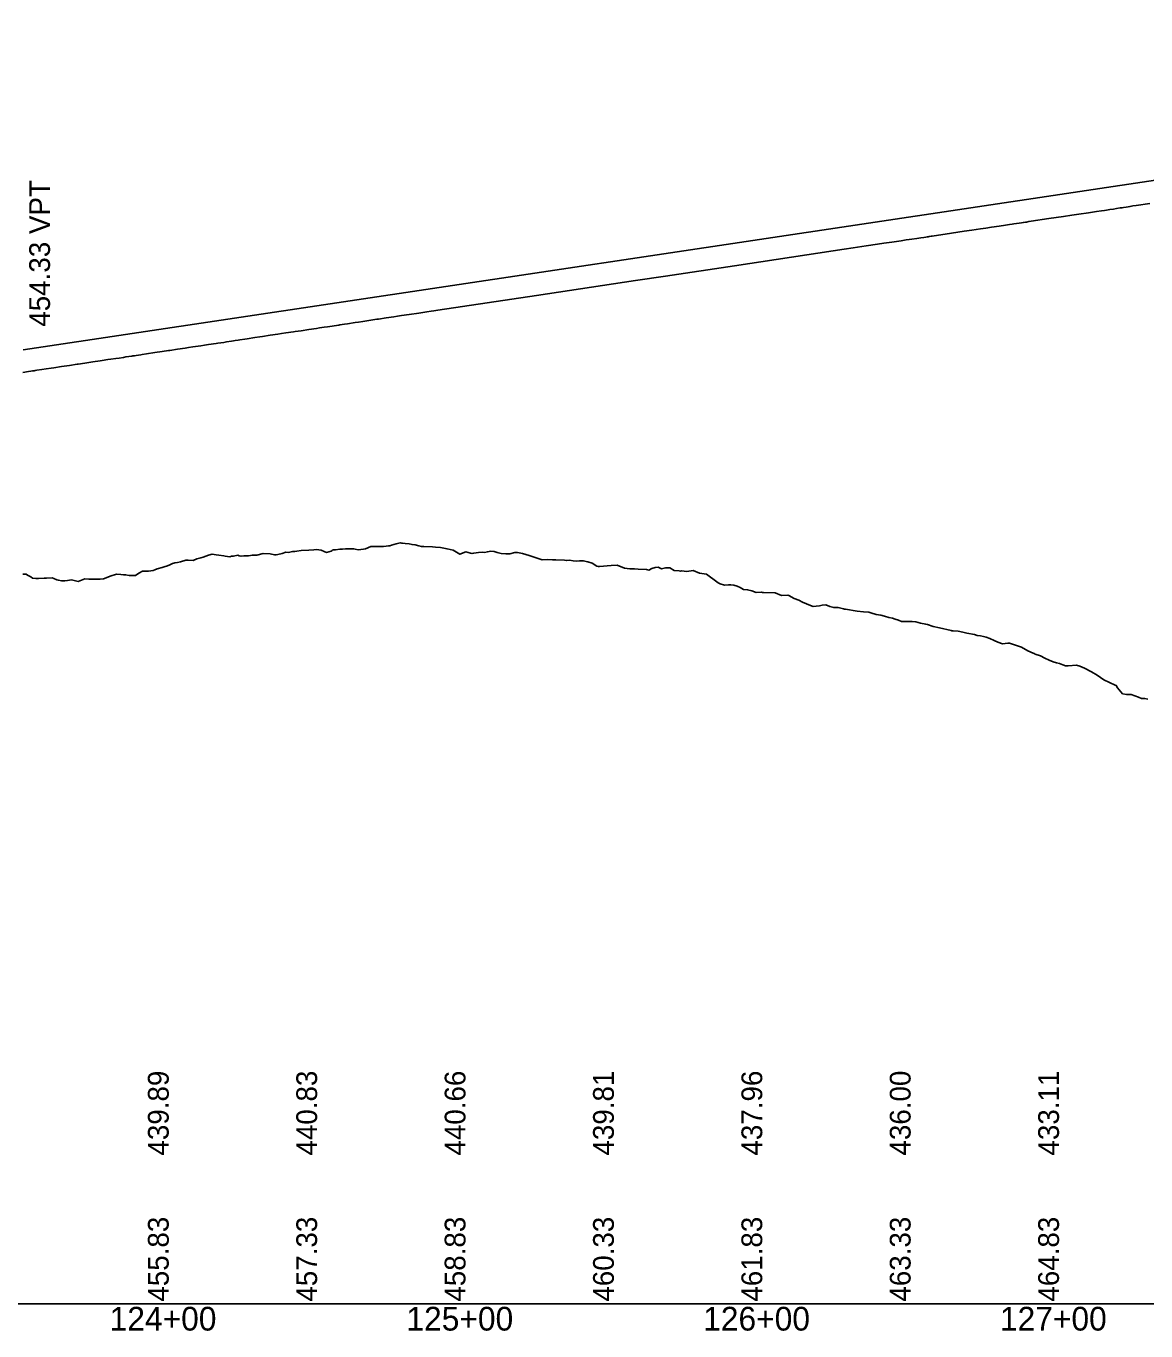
# Model space of a CAD drawing. Extents: x 2017200 to 2047700, y 854850 to 893350.
# Drawn here: x 2021850.9 to 2022228.3, y 865090.9 to 865530.8 of the extents above; entities that cross this region are included whole.
import ezdxf

# ---------------------------------------------------------------- set-up
doc = ezdxf.new("R2010")
doc.units = 0
for name, color, linetype in [('RD_DDB_Profile_Elev', 7, 'Continuous'), ('RD_DDB_Profile_EX', 7, 'Continuous'), ('RD_DDB_Profile_PR', 7, 'Continuous'), ('RD_DDB_StaTX', 7, 'Continuous'), ('RD_DDB_StripGrade', 7, 'Continuous'), ('RD_GPK_Profile_Cell', 7, 'Continuous')]:
    doc.layers.add(name, color=color, linetype=linetype)

msp = doc.modelspace()

# ---------------------------------------------------------------- linework, layer by layer
at = {"layer": 'RD_DDB_Profile_Elev'}
msp.add_lwpolyline([(2021849.9, 865414.03), (2021851.7, 865414.3), (2021852.5, 865414.42), (2021853.06, 865414.5), (2021853.66, 865414.59), (2021854.04, 865414.65), (2021854.57, 865414.73), (2021856.29, 865415), (2021857.71, 865415.21), (2021859.41, 865415.47), (2021860.32, 865415.6), (2021862.92, 865415.99), (2021864.66, 865416.25), (2021865.52, 865416.38), (2021868.13, 865416.77), (2021868.5, 865416.83), (2021870.73, 865417.16), (2021873.48, 865417.57), (2021875.94, 865417.94), (2021876.55, 865418.03), (2021878.54, 865418.33), (2021879.49, 865418.47), (2021881.14, 865418.71), (2021882.27, 865418.88), (2021883.75, 865419.1), (2021884.56, 865419.23), (2021885.52, 865419.37), (2021886.6, 865419.53), (2021886.93, 865419.58), (2021887.49, 865419.66), (2021888, 865419.74), (2021889.64, 865420), (2021890.09, 865420.07), (2021891.56, 865420.29), (2021894.32, 865420.7), (2021896.77, 865421.06), (2021898.95, 865421.39), (2021899.37, 865421.45), (2021901.97, 865421.84), (2021904.58, 865422.22), (2021905.65, 865422.38), (2021907.18, 865422.61), (2021908.02, 865422.74), (2021909.78, 865423), (2021911.09, 865423.19), (2021912.39, 865423.39), (2021914.99, 865423.77), (2021915.57, 865423.86), (2021917.59, 865424.16), (2021918.43, 865424.29), (2021920.2, 865424.55), (2021920.85, 865424.65), (2021921.37, 865424.73), (2021922.37, 865424.89), (2021922.99, 865425), (2021924.61, 865425.24), (2021925.41, 865425.36), (2021928.01, 865425.75), (2021929.74, 865426.01), (2021930.61, 865426.14), (2021933.22, 865426.53), (2021935.82, 865426.92), (2021936.96, 865427.09), (2021938.42, 865427.31), (2021941.03, 865427.7), (2021941.65, 865427.79), (2021943.63, 865428.09), (2021946.23, 865428.48), (2021948.84, 865428.87), (2021949.78, 865429.01), (2021951.44, 865429.26), (2021952.49, 865429.42), (2021954.04, 865429.65), (2021954.75, 865429.76), (2021956.29, 865430), (2021956.65, 865430.05), (2021958.26, 865430.29), (2021959.25, 865430.44), (2021961.86, 865430.83), (2021962.92, 865430.99), (2021964.46, 865431.22), (2021967.06, 865431.61), (2021969.19, 865431.93), (2021969.67, 865432), (2021972.27, 865432.39), (2021974.87, 865432.78), (2021976.05, 865432.96), (2021977.48, 865433.17), (2021980.08, 865433.56), (2021983.3, 865434.04), (2021984.68, 865434.25), (2021985.98, 865434.45), (2021987.47, 865434.67), (2021988.3, 865434.79), (2021989.64, 865435), (2022022.94, 865440), (2022056.28, 865445), (2022066.44, 865446.52), (2022089.61, 865450), (2022122.94, 865455), (2022126.59, 865455.55), (2022129.6, 865456), (2022134.04, 865456.66), (2022137.81, 865457.23), (2022140.02, 865457.56), (2022142.67, 865457.95), (2022144.26, 865458.19), (2022145.82, 865458.42), (2022147.51, 865458.67), (2022148.52, 865458.82), (2022149.47, 865458.96), (2022151.09, 865459.2), (2022152.47, 865459.4), (2022153.46, 865459.54), (2022154.12, 865459.64), (2022154.57, 865459.71), (2022154.89, 865459.75), (2022155.3, 865459.83), (2022155.91, 865459.94), (2022156.28, 865460), (2022162.74, 865460.96), (2022167.04, 865461.6), (2022169.68, 865461.99), (2022172.59, 865462.42), (2022174.4, 865462.69), (2022176.22, 865462.96), (2022178.84, 865463.34), (2022180.97, 865463.66), (2022182.38, 865463.86), (2022183.17, 865463.98), (2022183.74, 865464.07), (2022184.67, 865464.2), (2022185.59, 865464.34), (2022186.37, 865464.45), (2022186.97, 865464.54), (2022187.72, 865464.67), (2022188.05, 865464.72), (2022188.89, 865464.87), (2022189.61, 865465), (2022195.56, 865465.88), (2022200.5, 865466.62), (2022203.33, 865467.03), (2022205.71, 865467.38), (2022208.96, 865467.86), (2022211.6, 865468.25), (2022213.37, 865468.51), (2022214.37, 865468.65), (2022215.05, 865468.75), (2022216.19, 865468.92), (2022217.36, 865469.09), (2022218.38, 865469.23), (2022219.66, 865469.46), (2022220.25, 865469.54), (2022220.71, 865469.61), (2022221.59, 865469.76), (2022222.32, 865469.89), (2022222.94, 865470), (2022223.89, 865470.14), (2022224.99, 865470.3), (2022225.82, 865470.43), (2022226.63, 865470.54), (2022228.04, 865470.74), (2022229.58, 865470.96)], dxfattribs=at)
at = {"layer": 'RD_DDB_Profile_EX'}
msp.add_lwpolyline([(2021849.9, 865346.06), (2021850.98, 865345.96), (2021851.41, 865345.64), (2021852.5, 865345.05), (2021853.15, 865344.69), (2021854.24, 865344.52), (2021855.11, 865344.57), (2021857.06, 865344.69), (2021857.79, 865344.6), (2021859.68, 865344.76), (2021860.32, 865344.52), (2021861.34, 865344.13), (2021861.85, 865343.96), (2021862.92, 865343.79), (2021864.03, 865343.8), (2021864.91, 865343.86), (2021865.52, 865343.96), (2021866.2, 865344.07), (2021868.48, 865343.57), (2021870.73, 865344.42), (2021872.06, 865344.32), (2021873.33, 865344.29), (2021873.68, 865344.28), (2021875.94, 865344.33), (2021877.03, 865344.41), (2021878.54, 865345), (2021879.26, 865345.28), (2021881.36, 865345.98), (2021882.87, 865345.89), (2021883.75, 865345.82), (2021884.49, 865345.81), (2021885.68, 865345.61), (2021886.5, 865345.54), (2021887.84, 865345.54), (2021888.95, 865346.29), (2021890.13, 865347.04), (2021891.56, 865347), (2021892.16, 865346.99), (2021893.77, 865347.28), (2021894.32, 865347.52), (2021895.1, 865347.75), (2021896.77, 865348.25), (2021897.43, 865348.47), (2021898.63, 865348.77), (2021899.37, 865349.13), (2021900.33, 865349.59), (2021900.78, 865349.7), (2021901.1, 865349.79), (2021901.97, 865349.98), (2021902.93, 865350.17), (2021904.78, 865350.77), (2021905.08, 865350.69), (2021905.52, 865350.72), (2021907.24, 865350.62), (2021908.47, 865351.14), (2021909.78, 865351.53), (2021910.66, 865351.78), (2021912.39, 865352.39), (2021913.68, 865352.75), (2021914.99, 865352.56), (2021915.88, 865352.43), (2021917.59, 865352.17), (2021917.98, 865352.11), (2021919.6, 865351.89), (2021920.2, 865352.02), (2021920.82, 865352.09), (2021922.27, 865352.4), (2021922.8, 865352.23), (2021923.34, 865352.05), (2021924.41, 865352.24), (2021925.41, 865352.17), (2021925.84, 865352.14), (2021926.56, 865352.27), (2021927.09, 865352.36), (2021928.01, 865352.41), (2021928.7, 865352.44), (2021930.85, 865352.94), (2021933.22, 865352.81), (2021934.63, 865352.55), (2021935.12, 865352.49), (2021935.82, 865352.68), (2021937.26, 865353.02), (2021938.42, 865353.43), (2021939.4, 865353.34), (2021940.67, 865353.6), (2021941.03, 865353.62), (2021941.54, 865353.66), (2021942.21, 865353.79), (2021943.68, 865354.03), (2021946.23, 865354.15), (2021947.86, 865354.22), (2021948.84, 865354.28), (2021950.37, 865354.14), (2021951.44, 865353.67), (2021952.22, 865353.32), (2021953.7, 865353.78), (2021954.04, 865354), (2021954.35, 865354.19), (2021955.17, 865354.26), (2021956.65, 865354.48), (2021957.55, 865354.4), (2021958.62, 865354.53), (2021959.25, 865354.52), (2021959.94, 865354.51), (2021961.42, 865354.49), (2021961.86, 865354.41), (2021962.89, 865354.23), (2021964.67, 865354.43), (2021965.3, 865354.51), (2021967.15, 865355.36), (2021969.67, 865355.37), (2021971.41, 865355.33), (2021972.27, 865355.43), (2021973.12, 865355.53), (2021973.54, 865355.58), (2021974.04, 865355.79), (2021974.87, 865355.99), (2021975.67, 865356.18), (2021977.04, 865356.57), (2021977.48, 865356.48), (2021977.8, 865356.42), (2021978.68, 865356.3), (2021980.08, 865356.21), (2021980.99, 865355.98), (2021982.05, 865355.89), (2021983.3, 865355.56), (2021984.18, 865355.33), (2021984.94, 865355.34), (2021987.92, 865355.24), (2021988.88, 865355.11), (2021990.57, 865355), (2021992.83, 865354.5), (2021994.82, 865354.06), (2021997.15, 865352.72), (2021999.08, 865353.48), (2022000.73, 865353.12), (2022001.21, 865352.94), (2022001.77, 865353.09), (2022003.34, 865353.34), (2022004.68, 865353.47), (2022005.46, 865353.36), (2022006.38, 865353.55), (2022007.59, 865353.78), (2022008.63, 865353.62), (2022009.72, 865353.26), (2022011, 865353.01), (2022012.58, 865352.81), (2022013.98, 865352.86), (2022015.61, 865353.27), (2022016.1, 865353.33), (2022016.52, 865353.29), (2022018.23, 865352.92), (2022020.47, 865352.34), (2022022.49, 865351.65), (2022024.85, 865350.83), (2022026.74, 865350.94), (2022028.37, 865350.85), (2022029.46, 865350.86), (2022032.32, 865350.75), (2022033.13, 865350.61), (2022034.08, 865350.68), (2022035.26, 865350.51), (2022036.27, 865350.41), (2022037.39, 865350.54), (2022038.7, 865350.54), (2022040.21, 865350.16), (2022041.64, 865349.7), (2022043.31, 865348.72), (2022043.77, 865348.63), (2022044.16, 865348.55), (2022048.11, 865348.89), (2022050.15, 865349.07), (2022052.54, 865348.08), (2022054.41, 865347.85), (2022056.01, 865347.84), (2022057.16, 865347.74), (2022059.96, 865347.54), (2022060.8, 865347.33), (2022061.78, 865347.89), (2022062.92, 865348.23), (2022063.9, 865348.34), (2022065.05, 865347.75), (2022066.39, 865348.12), (2022067.85, 865348.13), (2022069.31, 865347.24), (2022071.01, 865347.16), (2022071.44, 865347.06), (2022071.8, 865347.12), (2022073.56, 865346.86), (2022075.75, 865347.21), (2022077.82, 865346.31), (2022080.24, 865346.05), (2022083.65, 865343.44), (2022084.2, 865343.07), (2022084.86, 865342.73), (2022086.33, 865342.32), (2022087.6, 865342.43), (2022088.46, 865342.46), (2022089.47, 865342.35), (2022090.59, 865341.91), (2022091.54, 865341.55), (2022092.72, 865340.78), (2022094.09, 865340.77), (2022095.49, 865340.43), (2022096.97, 865339.85), (2022098.71, 865339.94), (2022099.1, 865339.88), (2022099.44, 865339.84), (2022103.39, 865339.72), (2022105.49, 865338.78), (2022107.61, 865338.94), (2022107.94, 865338.83), (2022109.74, 865337.76), (2022111.29, 865337.21), (2022112.55, 865336.54), (2022115.23, 865335.43), (2022116.13, 865335.14), (2022117.17, 865335.27), (2022118.26, 865335.33), (2022119.18, 865335.53), (2022120.38, 865335.72), (2022121.79, 865335.15), (2022123.13, 865334.72), (2022124.64, 865334.72), (2022126.4, 865334.3), (2022126.77, 865334.17), (2022127.08, 865334.15), (2022131.03, 865333.55), (2022133.15, 865333.35), (2022134.98, 865333.18), (2022135.28, 865333.07), (2022135.64, 865332.98), (2022137.41, 865332.44), (2022138.93, 865332.19), (2022140.25, 865331.9), (2022141.66, 865331.36), (2022142.87, 865331.16), (2022143.79, 865330.79), (2022144.87, 865330.45), (2022145.92, 865330.09), (2022146.82, 865330.07), (2022149.48, 865330.05), (2022150.77, 865329.91), (2022152.31, 865329.48), (2022154.1, 865329.11), (2022154.72, 865329.01), (2022156.56, 865328.33), (2022158.72, 865327.95), (2022162.62, 865326.97), (2022162.95, 865326.95), (2022163.33, 865326.88), (2022165.07, 865326.74), (2022166.56, 865326.48), (2022167.95, 865326.11), (2022170.51, 865325.61), (2022171.46, 865325.32), (2022172.56, 865325.17), (2022173.59, 865324.94), (2022174.46, 865324.73), (2022175.72, 865324.34), (2022177.18, 865323.61), (2022178.41, 865323.11), (2022179.97, 865322.57), (2022181.8, 865322.71), (2022182.36, 865322.74), (2022185.68, 865321.66), (2022186.41, 865321.41), (2022188.48, 865320.16), (2022190.26, 865319.35), (2022190.61, 865319.28), (2022191.03, 865319.06), (2022192.74, 865318.43), (2022194.2, 865317.65), (2022195.65, 865317.02), (2022197, 865316.45), (2022198.15, 865316.15), (2022199.12, 865315.86), (2022200.26, 865315.45), (2022201.25, 865315.14), (2022202.1, 865315.15), (2022204.88, 865315.37), (2022206.05, 865315.03), (2022207.64, 865314.27), (2022210, 865313.12), (2022211.89, 865311.97), (2022214.11, 865310.4), (2022217.89, 865308.58), (2022218.28, 865308.45), (2022218.73, 865307.66), (2022220.41, 865305.66), (2022221.84, 865305.41), (2022223.34, 865305.45), (2022225.79, 865304.58), (2022226.79, 865304.14), (2022227.96, 865304.06), (2022228.92, 865303.87)], dxfattribs=at)
at = {"layer": 'RD_DDB_Profile_PR'}
msp.add_line((2021850, 865421.65), (2022577.5, 865530.78), dxfattribs=at)
at = {"layer": 'RD_GPK_Profile_Cell'}
msp.add_line((2020500, 865100), (2029700, 865100), dxfattribs=at)

# ---------------------------------------------------------------- texts
at = {"layer": 'RD_DDB_StaTX'}
for s, p in [('124+00', (2021879.1, 865091)), ('124+00', (2021879.1, 865091)), ('125+00', (2021979.1, 865091)), ('125+00', (2021979.1, 865091)), ('126+00', (2022079.1, 865091)), ('126+00', (2022079.1, 865091)), ('127+00', (2022179.1, 865091)), ('127+00', (2022179.1, 865091))]:
    msp.add_text(s, height=8, dxfattribs=at).set_placement(p)
at = {"layer": 'RD_DDB_StripGrade'}
for s, p in [('454.33 VPT', (2021859, 865429.43)), ('439.89', (2021899, 865150)), ('440.83', (2021949, 865150)), ('440.66', (2021999, 865150)), ('439.81', (2022049, 865150)), ('437.96', (2022099, 865150)), ('436.00', (2022149, 865150)), ('433.11', (2022199, 865150)), ('455.83', (2021899, 865100.75)), ('457.33', (2021949, 865100.75)), ('458.83', (2021999, 865100.75)), ('460.33', (2022049, 865100.75)), ('461.83', (2022099, 865100.75)), ('463.33', (2022149, 865100.75)), ('464.83', (2022199, 865100.75))]:
    msp.add_text(s, height=7, rotation=90, dxfattribs=at).set_placement(p)

doc.saveas('drawing.dxf')
